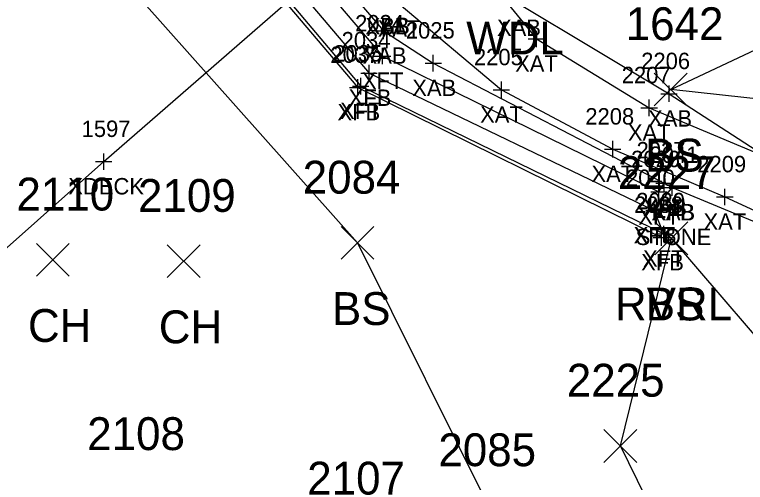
# Model space of a CAD drawing. Extents: x 1647133 to 1649138, y 411736 to 414924.
# Drawn here: x 1648964.63 to 1649009.12, y 412179.99 to 412208.47 of the extents above; entities that cross this region are included whole.
import ezdxf

# ---------------------------------------------------------------- set-up
doc = ezdxf.new("R2010")
doc.units = 0
for name, color, linetype in [('B_A', 7, 'Continuous'), ('B_C', 7, 'Continuous'), ('B_I', 7, 'Continuous'), ('B_TIC', 7, 'Continuous'), ('BELB', 7, 'Continuous'), ('BFT', 7, 'Continuous'), ('BSUBM', 7, 'Continuous'), ('L_A', 7, 'Continuous'), ('L_I', 7, 'Continuous'), ('L_TIC', 7, 'Continuous'), ('LAWE', 7, 'Continuous'), ('LELB', 7, 'Continuous')]:
    doc.layers.add(name, color=color, linetype=linetype)

msp = doc.modelspace()

# ---------------------------------------------------------------- linework, layer by layer
at = {"layer": 'B_TIC'}
for p, q in [((1648987.095, 412207.478), (1648987.171, 412207.478)), ((1648996.394, 412206.994), (1648996.47, 412206.994)), ((1648987.029, 412205.95), (1648987.104, 412205.95)), ((1648990.122, 412205.514), (1648990.197, 412205.514)), ((1648986.209, 412204.915), (1648986.284, 412204.915)), ((1648985.524, 412204.036), (1648985.6, 412204.036)), ((1648985.701, 412204.116), (1648985.777, 412204.116)), ((1648994.266, 412203.891), (1648994.341, 412203.891)), ((1649004.477, 412203.654), (1649004.552, 412203.654)), ((1649003.264, 412202.795), (1649003.339, 412202.795)), ((1649001.045, 412200.278), (1649001.121, 412200.278)), ((1648970.058, 412199.522), (1648970.134, 412199.522)), ((1649004.167, 412198.216), (1649004.242, 412198.216)), ((1649004.167, 412198.216), (1649004.242, 412198.216)), ((1649003.86, 412197.685), (1649003.936, 412197.685)), ((1649004.668, 412197.942), (1649004.744, 412197.942)), ((1649004.668, 412197.942), (1649004.744, 412197.942)), ((1649007.867, 412197.371), (1649007.943, 412197.371)), ((1649003.567, 412196.539), (1649003.643, 412196.539)), ((1649003.567, 412196.539), (1649003.643, 412196.539)), ((1649004.147, 412195.12), (1649004.223, 412195.12)), ((1649004.016, 412194.899), (1649004.092, 412194.899))]:
    msp.add_line(p, q, dxfattribs=at)
for points in [[(1648987.092, 412206.978), (1648987.092, 412207.978)], [(1648986.592, 412207.478), (1648987.592, 412207.478)], [(1648996.391, 412206.494), (1648996.391, 412207.494)], [(1648995.891, 412206.994), (1648996.891, 412206.994)], [(1648987.025, 412205.45), (1648987.025, 412206.45)], [(1648986.525, 412205.95), (1648987.525, 412205.95)], [(1648990.118, 412205.014), (1648990.118, 412206.014)], [(1648986.205, 412204.415), (1648986.205, 412205.415)], [(1648989.618, 412205.514), (1648990.618, 412205.514)], [(1648985.705, 412204.915), (1648986.705, 412204.915)], [(1648985.521, 412203.536), (1648985.521, 412204.536)], [(1648985.698, 412203.616), (1648985.698, 412204.616)], [(1648994.262, 412203.391), (1648994.262, 412204.391)], [(1648985.021, 412204.036), (1648986.021, 412204.036)], [(1648985.198, 412204.116), (1648986.198, 412204.116)], [(1648993.762, 412203.891), (1648994.762, 412203.891)], [(1649004.473, 412203.154), (1649004.473, 412204.154)], [(1649003.973, 412203.654), (1649004.973, 412203.654)], [(1649003.26, 412202.295), (1649003.26, 412203.295)], [(1649002.76, 412202.795), (1649003.76, 412202.795)], [(1649001.042, 412199.778), (1649001.042, 412200.778)], [(1649000.542, 412200.278), (1649001.542, 412200.278)], [(1648970.055, 412199.022), (1648970.055, 412200.022)], [(1648969.555, 412199.522), (1648970.555, 412199.522)], [(1649004.163, 412197.716), (1649004.163, 412198.716)], [(1649004.163, 412197.716), (1649004.163, 412198.716)], [(1649003.663, 412198.216), (1649004.663, 412198.216)], [(1649003.663, 412198.216), (1649004.663, 412198.216)], [(1649003.857, 412197.185), (1649003.857, 412198.185)], [(1649004.665, 412197.442), (1649004.665, 412198.442)], [(1649004.665, 412197.442), (1649004.665, 412198.442)], [(1649003.357, 412197.685), (1649004.357, 412197.685)], [(1649004.165, 412197.942), (1649005.165, 412197.942)], [(1649004.165, 412197.942), (1649005.165, 412197.942)], [(1649007.864, 412196.871), (1649007.864, 412197.871)], [(1649007.364, 412197.371), (1649008.364, 412197.371)], [(1649003.564, 412196.039), (1649003.564, 412197.039)], [(1649003.564, 412196.039), (1649003.564, 412197.039)], [(1649003.064, 412196.539), (1649004.064, 412196.539)], [(1649003.064, 412196.539), (1649004.064, 412196.539)], [(1649004.013, 412194.399), (1649004.013, 412195.399)], [(1649004.144, 412194.62), (1649004.144, 412195.62)], [(1649003.644, 412195.12), (1649004.644, 412195.12)], [(1649003.513, 412194.899), (1649004.513, 412194.899)]]:
    msp.add_lwpolyline(points, dxfattribs=at)
at = {"layer": 'BELB'}
msp.add_lwpolyline([(1648856.366, 412097.638), (1648904.081, 412141.155), (1648932.964, 412166.557), (1648970.055, 412199.522), (1648985.33, 412212.818), (1648974.892, 412224.907)], dxfattribs=at)
at = {"layer": 'BFT'}
for points in [[(1648969.053, 412251.503), (1648967.008, 412251.583), (1648967.16, 412237.956), (1648967.307, 412234.686), (1648967.339, 412227.16), (1648986.205, 412204.915), (1649003.564, 412196.539), (1649004.665, 412197.942)], [(1648969.525, 412251.264), (1648968.489, 412251.237), (1648968.622, 412227.573), (1648987.025, 412205.95), (1649003.857, 412197.685), (1649004.163, 412198.216)], [(1648967.307, 412234.686), (1648966.291, 412234.321), (1648966.579, 412226.766), (1648985.698, 412204.116), (1649004.144, 412195.12), (1649003.564, 412196.539)], [(1648966.022, 412234.167), (1648966.193, 412226.664), (1648972.524, 412219.358), (1648985.521, 412204.036), (1649004.013, 412194.899)]]:
    msp.add_lwpolyline(points, dxfattribs=at)
at = {"layer": 'BSUBM'}
for points in [[(1648980.212, 412272.224), (1648969.681, 412271.317), (1648969.261, 412266.421), (1648968.934, 412254.381), (1648969.053, 412251.503), (1648969.525, 412251.264), (1648969.788, 412227.697), (1648987.092, 412207.478), (1648990.118, 412205.514), (1649004.163, 412198.216), (1649004.665, 412197.942), (1649016.348, 412193.098), (1649025.312, 412183.014), (1649046.031, 412166.296)], [(1648999.252, 412222.01), (1649000.017, 412221.012), (1648993.191, 412215.427), (1648991.492, 412213.898), (1648995.274, 412209.174), (1649004.473, 412203.654), (1649010.456, 412199.768)], [(1648988.03, 412209.126), (1648991.506, 412213.009), (1648996.391, 412206.994), (1649003.26, 412202.795), (1649010.456, 412199.768), (1649020.036, 412194.102), (1649031.356, 412182.024), (1649047.922, 412168.893)], [(1648988.03, 412209.126), (1648994.262, 412203.891), (1649001.042, 412200.278), (1649007.864, 412197.371), (1649018.249, 412192.591), (1649029.488, 412180.719), (1649045.657, 412167.83), (1649047.922, 412168.893)]]:
    msp.add_lwpolyline(points, dxfattribs=at)
at = {"layer": 'L_TIC'}
for points in [[(1649003.571, 412202.917), (1649005.571, 412204.917)], [(1649005.571, 412202.917), (1649003.571, 412204.917)], [(1649003.61, 412193.853), (1649005.61, 412195.853)], [(1649005.61, 412193.853), (1649003.61, 412195.853)], [(1649003.61, 412193.853), (1649005.61, 412195.853)], [(1649005.61, 412193.853), (1649003.61, 412195.853)], [(1648984.506, 412193.573), (1648986.506, 412195.573)], [(1648986.506, 412193.573), (1648984.506, 412195.573)], [(1648965.952, 412192.543), (1648967.952, 412194.543)], [(1648967.952, 412192.543), (1648965.952, 412194.543)], [(1648973.918, 412192.46), (1648975.918, 412194.46)], [(1648975.918, 412192.46), (1648973.918, 412194.46)], [(1649000.505, 412181.211), (1649002.505, 412183.211)], [(1649002.505, 412181.211), (1649000.505, 412183.211)]]:
    msp.add_lwpolyline(points, dxfattribs=at)
at = {"layer": 'LAWE'}
msp.add_lwpolyline([(1649047.938, 412109.386), (1649033.519, 412127.621), (1649023.498, 412153.641), (1649007.679, 412169.628), (1649001.505, 412182.211), (1649004.61, 412194.853)], dxfattribs=at)
at = {"layer": 'LELB'}
for points in [[(1648910.338, 412307.481), (1648923.401, 412285.734), (1648930.01, 412277.072), (1648939.665, 412266.792), (1648945.948, 412259.157), (1648943.1, 412258.499), (1648935.158, 412254.464), (1648928.495, 412254.282), (1648924.406, 412254.203), (1648925.497, 412246.049), (1648929.643, 412242.699), (1648937.314, 412237.257), (1648939.737, 412232.884), (1648942.092, 412231.581), (1648961.498, 412231.409), (1648963.583, 412219.195), (1648985.506, 412194.573), (1648993.764, 412177.977), (1649005.161, 412156.054), (1649014.951, 412138.525), (1649020.659, 412120.018), (1649027.353, 412106.948), (1649037.638, 412094.49)], [(1649076.641, 412139.604), (1649064.069, 412155.759), (1649043.704, 412175.556), (1649025.511, 412201.612), (1649004.571, 412203.917), (1649026.54, 412214.258), (1649035.268, 412210.483), (1649038.43, 412209.721), (1649056.28, 412213.622), (1649076.026, 412192.594), (1649101.777, 412169.939)], [(1649055.656, 412117.815), (1649039.256, 412150.575), (1649031.138, 412167.605), (1649021.557, 412178.437), (1649012.393, 412185.804), (1649004.61, 412194.853)]]:
    msp.add_lwpolyline(points, dxfattribs=at)

# ---------------------------------------------------------------- texts
at = {"layer": 'B_A'}
for s, p in [('XAB', (1648985.981, 412207.275)), ('XBS', (1648986.001, 412207.275)), ('XAT', (1648986.735, 412207.126)), ('XAT', (1648986.735, 412207.126)), ('XAB', (1648993.994, 412207.174)), ('XAB', (1648985.812, 412205.478)), ('XAT', (1648995.096, 412204.994)), ('XFT', (1648985.769, 412203.95)), ('XAB', (1648988.839, 412203.514)), ('XFB', (1648984.965, 412202.915)), ('XFB', (1648984.281, 412202.036)), ('XFT', (1648984.442, 412202.116)), ('XAT', (1648992.967, 412201.891)), ('XAB', (1649003.194, 412201.654)), ('XAT', (1649001.965, 412200.795)), ('XAT', (1648999.747, 412198.278)), ('XDECK', (1648967.897, 412197.522)), ('XAB', (1649002.884, 412196.216)), ('XFT', (1649002.907, 412196.216)), ('XAB', (1649003.385, 412195.942)), ('XFB', (1649003.425, 412195.942)), ('XFT', (1649002.601, 412195.685)), ('XAT', (1649006.568, 412195.371)), ('XFT', (1649002.308, 412194.539)), ('XFB', (1649002.324, 412194.539)), ('XFT', (1649002.888, 412193.12)), ('XFB', (1649002.773, 412192.899))]:
    msp.add_text(s, height=1, dxfattribs=at).set_placement(p)
at = {"layer": 'B_C'}
msp.add_text('STONE', height=1, dxfattribs=at).set_placement((1649002.437, 412194.442))
at = {"layer": 'B_I'}
for s, p in [('2024', (1648985.356, 412207.45)), ('2025', (1648988.449, 412207.014)), ('2034', (1648984.536, 412206.415)), ('2037', (1648983.852, 412205.536)), ('2035', (1648984.029, 412205.616)), ('2205', (1648992.593, 412205.391)), ('2206', (1649002.776, 412205.154)), ('2207', (1649001.591, 412204.295)), ('2208', (1648999.373, 412201.778)), ('1597', (1648968.708, 412201.022)), ('2027', (1649002.494, 412199.716)), ('2027', (1649002.494, 412199.716)), ('2041', (1649003.279, 412199.442)), ('2041', (1649003.279, 412199.442)), ('2026', (1649002.16, 412199.185)), ('2209', (1649006.19, 412198.871)), ('2040', (1649001.851, 412198.039)), ('2040', (1649001.851, 412198.039)), ('2039', (1649002.47, 412196.62)), ('2038', (1649002.344, 412196.399))]:
    msp.add_text(s, height=1, dxfattribs=at).set_placement(p)
at = {"layer": 'L_A'}
for s, p in [('WDL', (1648992.121, 412206.046)), ('BS', (1649003.012, 412198.917)), ('RVRL', (1649001.177, 412189.853)), ('BS', (1649003.051, 412189.853)), ('BS', (1648983.947, 412189.573)), ('CH', (1648965.44, 412188.543)), ('CH', (1648973.406, 412188.46))]:
    msp.add_text(s, height=2, dxfattribs=at).set_placement(p)
at = {"layer": 'L_I'}
for s, p in [('1642', (1649001.831, 412206.917)), ('2227', (1649001.35, 412197.853)), ('2227', (1649001.35, 412197.853)), ('2084', (1648982.167, 412197.573)), ('2110', (1648964.739, 412196.543)), ('2109', (1648972.139, 412196.46)), ('2225', (1648998.245, 412185.211)), ('2108', (1648969.047, 412181.958)), ('2085', (1648990.425, 412180.977)), ('2107', (1648982.443, 412179.248))]:
    msp.add_text(s, height=2, dxfattribs=at).set_placement(p)

doc.saveas('drawing.dxf')
